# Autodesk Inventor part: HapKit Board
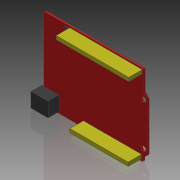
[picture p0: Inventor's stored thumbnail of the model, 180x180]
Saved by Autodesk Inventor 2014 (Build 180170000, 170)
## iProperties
Created: 2015-07
Part Number: HapKit Board
Material: Generic
Document SubType Name: Modeling
Designer: Brad Factor
Density: 1 g/cm^3
Appearance: Default
Author: Brad Factor
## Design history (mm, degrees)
sketch "Sketch1"
  geometry: L1 (-32.988, 26.74)-(32.988, 26.74); L2 (32.988, 26.74)-(32.988, 13.329); L3 (32.988, 13.329)-(35.541, 10.649); L4 (35.541, 10.649)-(35.541, -21.52); L5 (35.541, -21.52)-(32.728, -24.2); L6 (32.728, -24.2)-(32.728, -26.74); L7 (32.728, -26.74)-(-32.988, -26.74); L8 (-32.988, -26.74)-(-32.988, 26.74); L9 (-32.988, 26.74)-(32.728, -26.74); L10 (32.988, 26.74)-(-32.988, -26.74); 2 further points
  constraints: 20 end point, 4 vertical, 2 horizontal, 1 coincident, 1 midpoint, 1 perpendicular
  dimensions: "d0" = 53.4797 distance of L7.end L1.start; "d1" = 65.9765 distance of L1.start L1.end; "d2" = 68.5292 distance between parallel lines of L4 L8; "d3" = 2.6797 vertical distance of L3.end L2.end; "d4" = 2.6797 vertical distance of L5.end L4.end; "d5" = 37.5285 vertical distance of L5.end L2.end; "d6" = 2.54 distance of L5.end L6.end
extrude "PCB" new body sketch "Sketch1" distance "d7" = 1.1176; taper "d8" = 0 deg
sketch "Sketch2"
  geometry: L1 (32.988, 26.74)-(-32.988, 26.74) reference; L2 (-32.988, 26.74)-(-32.988, -26.74) reference; L3 (-32.988, -26.74)-(32.728, -26.74) reference; L4 (32.728, -24.2)-(35.541, -21.52) reference; L5 (35.541, -21.52)-(35.541, 10.649) reference; L6 (35.541, 10.649)-(32.988, 13.329) reference; L7 (32.988, 13.329)-(32.988, 26.74) reference; L8 (34.563, 11.676)-(34.563, -22.452); L9 (36.461, -20.644)-(-32.988, -20.644); L10 (35.541, 10.738)-(-32.988, 10.738); L11 (-32.988, 25.775)-(32.988, 25.775); L12 (-19.425, 26.74)-(-19.425, -26.74); C1 r 1.6 at (32.963, 9.138); C2 r 1.6 at (32.963, -19.044); C3 r 1.6 at (-17.824, 24.174); 1 further point
  constraints: 10 end point, 10 point on line, 6 tangent, 3 centre point, 3 horizontal, 2 equal radius, 2 vertical
  dimensions: "d9" = 3.2004 diameter of C1; "d10" = 0.9779 distance between parallel lines of L8 L5; "d11" = 6.096 distance between parallel lines of L3 L9; "d12" = 16.002 distance between parallel lines of L1 L10; "d13" = 0.9652 distance between parallel lines of L1 L11; "d14" = 13.5636 distance between parallel lines of L2 L12; "d40" = 28.1813 distance of C2.centre C1.centre (derived); "d41" = 7.6962 distance from line of L3 C2.centre (derived)
extrude "Screw Holes" cut sketch "Sketch2" stored distance "d15" = 1.1176; taper "d16" = 0 deg
sketch "Sketch3"
  geometry: L1 (-35.541, 10.649)-(-35.541, -21.52) reference; L2 (-32.728, -26.74)-(32.988, -26.74) reference; L3 (-3.359, -9.9)-(2.127, -9.9); L4 (2.127, -9.9)-(2.127, -14.091); L5 (2.127, -14.091)-(-3.359, -14.091); L6 (-3.359, -14.091)-(-3.359, -9.9); 1 further point
  constraints: 8 end point, 2 parallel, 1 horizontal, 1 perpendicular
  dimensions: "d17" = 5.4864 distance of L4.end L5.end; "d18" = 4.191 distance of L3.end L4.end; "d19" = 32.1818 distance between parallel lines of L1 L6; "d20" = 12.6492 distance between parallel lines of L2 L5
extrude "MR Sensor" join sketch "Sketch3" distance "d21" = 1.651; taper "d22" = 0 deg
sketch "Sketch4"
  geometry: L1 (-32.988, 26.74)-(-32.988, -26.74) reference; L2 (-32.988, -26.74)-(32.728, -26.74) reference; L3 (-22.854, -25.648)-(-34.233, -25.648); L4 (-34.233, -25.648)-(-34.233, -16.173); L5 (-34.233, -16.173)-(-22.854, -16.173); L6 (-22.854, -16.173)-(-22.854, -25.648); 1 further point
  constraints: 8 end point, 2 parallel, 1 horizontal, 1 perpendicular
  dimensions: "d23" = 11.3792 distance of L3.start L3.end; "d24" = 9.4742 distance of L3.end L4.end; "d25" = 1.2446 distance between parallel lines of L1 L4; "d26" = 1.0922 distance between parallel lines of L3 L2
extrude "Power Inlet" join sketch "Sketch4" distance "d27" = 7.2898; taper "d28" = 0 deg
sketch "Sketch5"
  geometry: L1 (-32.988, -26.74)-(32.728, -26.74) reference; L2 (32.728, -26.74)-(32.728, -24.2) reference; L3 (32.988, 13.329)-(32.988, 26.74) reference; L4 (32.988, 26.74)-(-32.988, 26.74) reference; L5 (-6.744, -22.854)-(31.687, -22.854); L6 (31.687, -22.854)-(31.687, -25.368); L7 (31.687, -25.368)-(-6.744, -25.368); L8 (-6.744, -25.368)-(-6.744, -22.854); L9 (-15.805, 25.902)-(32.15, 25.902); L10 (32.15, 25.902)-(32.15, 23.387); L11 (32.15, 23.387)-(-15.805, 23.387); L12 (-15.805, 23.387)-(-15.805, 25.902); 1 further point
  constraints: 16 end point, 4 parallel, 2 horizontal, 2 perpendicular
  dimensions: "d29" = 38.4302 distance of L6.end L7.end; "d30" = 2.5146 distance of L5.end L6.end; "d31" = 1.3716 distance between parallel lines of L1 L7; "d32" = 1.0414 distance between parallel lines of L2 L6; "d33" = 2.5146 distance of L9.end L10.end; "d34" = 47.9552 distance of L9.start L9.end; "d35" = 0.8382 distance between parallel lines of L4 L9; "d36" = 0.8382 distance between parallel lines of L3 L10
extrude "0.1\" Connector Headers" join sketch "Sketch5" distance "d37" = 8.9154; taper "d38" = 0 deg
fillet "1/32\" Fillets" dims "d39" = 0.79375
workplane "Work Plane1"
workplane "Work Plane2"
body "Solid1"
other parameters: "d42" = -2.0955, "d43" = -2.7432
